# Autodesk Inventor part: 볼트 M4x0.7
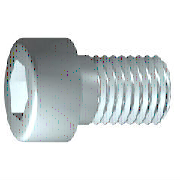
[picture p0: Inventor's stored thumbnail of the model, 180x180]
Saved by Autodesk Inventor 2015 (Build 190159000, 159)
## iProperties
IsCustomPart: 1
Created: 2015-10
Part Number: 볼트 M4x0.7
Material: 스테인리스강
Description: 6각머리 태핑 나사
Document SubType Name: Modeling
Standard: KS B 1003
Designer: mdu
Standards Organization: KS
Language: ko-KR
Size Designation: M 4 x 16
Categories: <MemberInstance><Categories><Category DisplayName="조임쇠" InternalName="e4da775c-781d-43d5-af7c-5136215cf5a6" Mnemonic="FSTN"><Category DisplayName="볼트" InternalN
Density: 8.08 g/cm^3
Mass: 2.70334 g
Surface Area: 3.81118 cm^2
Volume: 0.334572 cm^3
Appearance: 반광택
Author: mdu
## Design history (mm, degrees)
sketch "스케치1"
  geometry: L1 (-1, 0)-(16, 0); L2 (16, 0)-(16, 2); L3 (16, 2)-(1.75, 2); L4 (1.75, 2)-(1.32, 2); L5 (1.32, 2)-(0, 2); L6 (0, 2)-(0, 3.5); L7 (0, 3.5)-(-4, 3.5); L8 (-4, 3.5)-(-4, 1.732); L9 (-4, 1.732)-(-2, 1.732); L10 (-2, 1.732)-(-1, 0); L11 (-8, 0)-(20, 0) reference; L12 (0, -0.7)-(0, 4.2) reference; L13 (1.75, 2)-(0, 2)
  constraints: 22 end point, 6 parallel, 2 collinear, 2 perpendicular, 1 horizontal, 1 point on line
  dimensions: "d1" = 14.25 distance from line of L3.end L2 (= GEL); "d2" = 0.42952 distance of L4.end L3.end (computed from GAL); "d3" = 4 distance between parallel lines of L8 L6 (= KOH); "d4" = 2 distance of L8.end L9.end (= INTI); "d5" = 60 deg angle of L10 L1; "d6" = 4 diameter of L3 L1 (= GD); "d7" = 4 diameter of L5 L1 (= BDM); "d8" = 3.4641 diameter of L9 L1 (= 1.1547 x SW); "d9" = 7 diameter of L7 L1 (= KOD); "d26" = 16 distance between parallel lines of L12 L2 (= NLG)
revolve "본체" sketch "스케치1" stored, may be unused: angle "d10" = 90 deg
sketch "스케치2"
  geometry: L1 (0, -4.9)-(0, 4.9) reference; L2 (-4.9, 0)-(4.9, 0) reference; L3 (1.732, 0)-(0.866, -1.5); L4 (0.866, -1.5)-(-0.866, -1.5); L5 (-0.866, -1.5)-(-1.732, 0); L6 (-1.732, 0)-(-0.866, 1.5); L7 (-0.866, 1.5)-(0.866, 1.5); L8 (0.866, 1.5)-(1.732, 0); 2 further points
  constraints: 12 end point, 1 coincident, 1 horizontal alignment, 1 point on line, 12 other
extrude "슬롯" join sketch "스케치2" stored distance "d11" = 10; taper "d12" = 0 deg
workplane "Work Plane1"
fillet "Fillet2" dims "d30" = 0.1 (= R)
body "Solid1"
fillet "모깎기1" dims "d17" = 0.4 (= RR)
feature "스레드" dims "d13" = 14.25 (= GEL), "d14" = 0
chamfer "모따기1" distance "d15" = 0.42941 (= -0.5 x SPD + 0.5 x GD); stored, may be unused: second distance "d16" = 0.42941 (= GUL), angle "d27" = 45 deg
other parameters: "GD" = 4 (= NND) [user parameter; used in 2 equation terms], "NLG" = 16 [user parameter; used in 1 equation term], "GEL" = 14.25 [user parameter; used in 2 equation terms], "KOD" = 7 [user parameter; used in 1 equation term], "KOH" = 4 [user parameter; used in 1 equation term], "INTI" = 2 [user parameter; used in 1 equation term], "GAL" = 0.42941 (= 0.61345 x PTC) [user parameter; used in 1 equation term], "GUL" = 0.42941 (= 0.61345 x PTC) [user parameter; used in 1 equation term], "BDM" = 4 (= NND) [user parameter; used in 1 equation term], "SW" = 3 [user parameter; used in 2 equation terms], "RR" = 0.4 [user parameter; used in 1 equation term], "SPD" = 3.14117 (= NND - 1.2269 x PTC) [user parameter; used in 1 equation term], "d19" = 0, "d28" = 0, "d29" = 0, "R" = 0.1 [user parameter; used in 1 equation term], "PHH" = 0.2 [user parameter], "GD1" = 3.14117 (= THREADDIA - 1.2269 x PTC) [user parameter], "THREADDIA" = 4 [user parameter; used in 1 equation term], "FAWI" = 45 deg [user parameter], "TPU" = 14.28571 (computed from PTC) [user parameter], "PTC" = 0.7 [user parameter; used in 5 equation terms], "NND" = 4 [user parameter; used in 3 equation terms], "TOA" = 30 deg [user parameter], "E0" = 3.465 (= 1.155 x SW) [user parameter]
